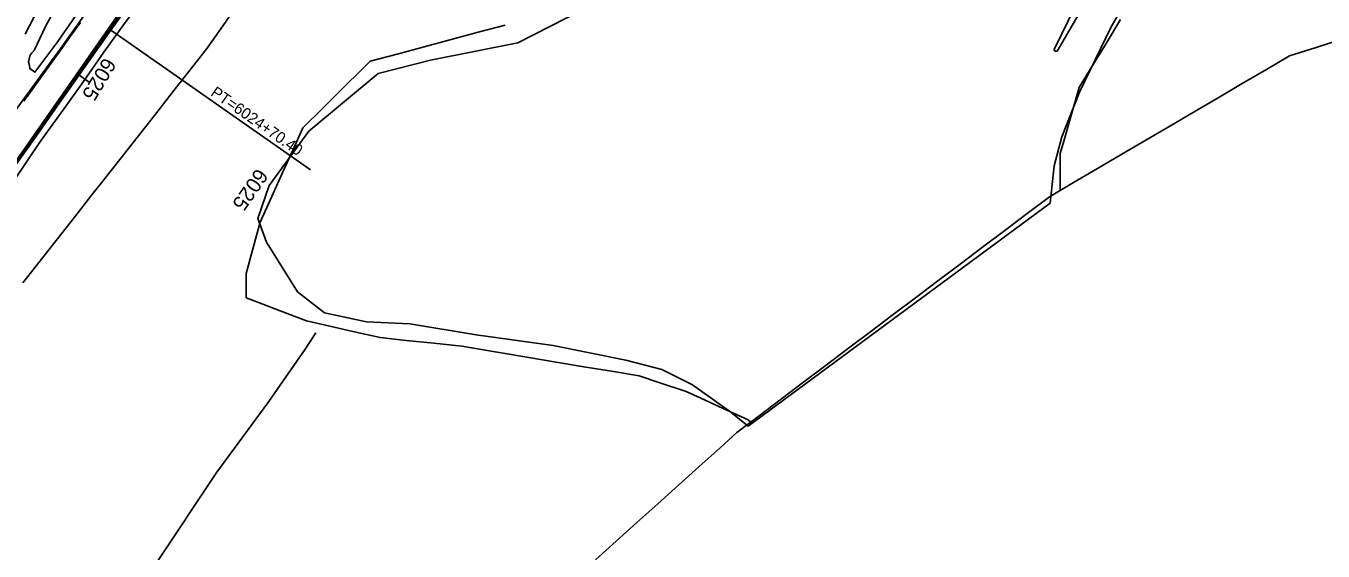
# Model space of a CAD drawing. Extents: x 2132221 to 2141942, y 535736 to 547298.
# Drawn here: x 2137298 to 2137994, y 538942 to 539223 of the extents above; entities that cross this region are included whole.
import ezdxf

# ---------------------------------------------------------------- set-up
doc = ezdxf.new("R2010")
doc.units = 0
for name, color, linetype in [('RD_EX_Conc', 7, 'Continuous'), ('RD_EX_Fence_Other', 7, 'Continuous'), ('RD_EX_H2O', 7, 'Continuous'), ('RD_EX_Misc', 7, 'Continuous'), ('RD_EX_Road', 7, 'Continuous'), ('RD_EX_VEG', 7, 'Continuous'), ('RD_HC_Cl', 7, 'Continuous'), ('RD_HC_Data', 7, 'Continuous'), ('RD_HC_Data_Tic', 7, 'Continuous'), ('RD_HC_TX_Sta50', 7, 'Continuous'), ('TOPO_E_TLIML-Line', 7, 'Continuous')]:
    doc.layers.add(name, color=color, linetype=linetype)

msp = doc.modelspace()

# ---------------------------------------------------------------- linework, layer by layer
at = {"layer": 'RD_EX_Conc'}
for points in [[(2137297.62, 539219.08), (2137309.33, 539241.89), (2137320.01, 539262.99), (2137332.61, 539287.08), (2137349.68, 539315.66)], [(2137386.22, 539279.28), (2137375.65, 539265.67), (2137364.42, 539250.49), (2137352.58, 539233.98), (2137342.73, 539219.91), (2137331.08, 539203.52), (2137316.82, 539183.44), (2137303.12, 539163.77), (2137293.03, 539149.45), (2137281.61, 539133.04), (2137267.61, 539113.07), (2137257.39, 539098.52), (2137236.65, 539069.06), (2137212.4, 539034.24), (2137197.5, 539013.03), (2137179.75, 538987.14)], [(2137362.94, 539275.45), (2137351.65, 539260.12), (2137339.72, 539243.51), (2137329.01, 539228.88), (2137318.09, 539213.54), (2137305.67, 539196.39), (2137289.35, 539173.96)]]:
    msp.add_lwpolyline(points, dxfattribs=at)
at = {"layer": 'RD_EX_Fence_Other'}
msp.add_lwpolyline([(2136945.37, 538272.3), (2136971.41, 538318.47), (2136997.08, 538363.8), (2137022.8, 538408.95), (2137051.26, 538458.29), (2137077.19, 538502.71), (2137097.8, 538537.44), (2137124.86, 538582.37), (2137152.04, 538626.83), (2137178.02, 538666.71), (2137198.91, 538695.64), (2137227.84, 538735.5), (2137257.45, 538774.75), (2137289.09, 538819.98), (2137317.7, 538861.51), (2137345.66, 538902.94), (2137367.4, 538934.33), (2137400.42, 538984.12), (2137428.26, 539021.95), (2137447.73, 539050.02), (2137453.51, 539058.83)], dxfattribs=at)
at = {"layer": 'RD_EX_H2O'}
msp.add_line((2137847.5, 539128.42), (2137685.45, 539008.68), dxfattribs=at)
for points in [[(2137886.46, 539286.47), (2137849.68, 539210.84), (2137849.93, 539210.04)], [(2137895.59, 539249.76), (2137880.13, 539223.04), (2137863.18, 539187.95), (2137853.74, 539164.07), (2137849.61, 539148.37), (2137847.5, 539128.42)], [(2137849.93, 539210.04), (2137851.22, 539210.04), (2137872.96, 539247.48)], [(2137685.45, 539008.68), (2137676.1, 539016.18), (2137655.58, 539030.97), (2137639.12, 539039.08), (2137619.9, 539044.12), (2137580.84, 539052.04), (2137539.51, 539057.84), (2137503.99, 539063.61), (2137480.64, 539064.8), (2137458.25, 539069.56), (2137443.74, 539080.87), (2137427.12, 539107.48), (2137422.46, 539120.23), (2137428.56, 539137.96), (2137449.83, 539167.12), (2137486.95, 539198.05), (2137515.1, 539205.14), (2137561.97, 539214.45), (2137596.87, 539232.3)]]:
    msp.add_lwpolyline(points, dxfattribs=at)
at = {"layer": 'RD_EX_Misc'}
for points in [[(2137351.05, 539232.89), (2137342.37, 539220.66), (2137333.7, 539208.42), (2137325.02, 539196.19), (2137323.9, 539194.61), (2137315.3, 539182.33), (2137306.69, 539170.04), (2137298.09, 539157.76), (2137289.48, 539145.47)], [(2137296.93, 539183.17), (2137302.42, 539190.8), (2137307.91, 539198.44), (2137313.4, 539206.07), (2137316.33, 539210.13), (2137321.82, 539217.77), (2137327.31, 539225.4)]]:
    msp.add_lwpolyline(points, dxfattribs=at)
at = {"layer": 'RD_EX_Road'}
for points in [[(2137371.7, 539292.54), (2137357.19, 539273.64), (2137342.52, 539253.53), (2137326.08, 539230.83), (2137315.06, 539215.22), (2137302.83, 539198.78), (2137300.08, 539200.59), (2137299.94, 539202.26), (2137299.34, 539204.04), (2137300.12, 539207.5), (2137301.1, 539209.13), (2137302.41, 539210.39), (2137308.71, 539223.55), (2137316.49, 539238.12), (2137321.07, 539246.25), (2137329.02, 539260.71), (2137341.13, 539281.49), (2137350.29, 539297.24), (2137356.91, 539308.32)], [(2137390.6, 539276.98), (2137381.06, 539264.66), (2137366.46, 539244.94), (2137351.69, 539226.13), (2137339.88, 539209.47), (2137328.84, 539193.7), (2137317.64, 539177.92), (2137305.73, 539161.76), (2137291.11, 539139.83), (2137277.39, 539118.75), (2137261.14, 539093.92), (2137244.5, 539069.57), (2137229.53, 539048.64), (2137216.9, 539030.62), (2137196.32, 539001.16), (2137178.95, 538975.86), (2137168.15, 538960.62)]]:
    msp.add_lwpolyline(points, dxfattribs=at)
at = {"layer": 'RD_EX_VEG'}
for points in [[(2137411.1, 539234.3), (2137402.48, 539222.02), (2137394.66, 539210.9), (2137385.4, 539199.1), (2137376.15, 539187.29), (2137366.89, 539175.49), (2137357.64, 539163.68), (2137348.38, 539151.88), (2137339.12, 539140.07), (2137333.42, 539132.81), (2137324.17, 539121), (2137314.91, 539109.2), (2137305.66, 539097.39), (2137296.4, 539085.59)], [(2137686.9, 539010.98), (2137685.4, 539012.17), (2137671.77, 539018.43), (2137658.14, 539024.7), (2137652.28, 539027.4), (2137638.02, 539032.05), (2137626.9, 539035.68), (2137612.11, 539038.18), (2137597.32, 539040.67), (2137582.53, 539043.16), (2137567.74, 539045.66), (2137552.95, 539048.15), (2137538.16, 539050.65), (2137531.82, 539051.71), (2137516.9, 539053.26), (2137501.98, 539054.81), (2137488.02, 539056.26), (2137473.4, 539059.62), (2137458.78, 539062.98), (2137448.49, 539065.34), (2137434.47, 539070.68), (2137420.45, 539076.01), (2137416.17, 539077.64), (2137416.17, 539090.73), (2137420.1, 539105.2), (2137423.65, 539118.25), (2137429.86, 539131.91), (2137436.07, 539145.56), (2137442.28, 539159.22), (2137446.62, 539168.76), (2137457.26, 539179.33), (2137467.9, 539189.9), (2137478.55, 539200.47), (2137482.67, 539204.56), (2137497.16, 539208.44), (2137511.65, 539212.32), (2137526.14, 539216.2), (2137540.63, 539220.07), (2137555.13, 539223.95)], [(2137885.29, 539226.92), (2137877.45, 539214.13), (2137869.6, 539201.35), (2137862.96, 539190.52), (2137858.84, 539176.09), (2137854.73, 539161.67), (2137852.82, 539154.97), (2137852.82, 539139.97), (2137852.82, 539135.21)]]:
    msp.add_lwpolyline(points, dxfattribs=at)
at = {"layer": 'RD_HC_Cl'}
msp.add_line((2137342.26, 539222.2), (2136996.48, 538726.24), dxfattribs=at)
msp.add_arc((2138238.15, 538594.85), 1093.7, 40.39109, 144.99812, dxfattribs=at)
at = {"layer": 'RD_HC_Data'}
msp.add_line((2137342.26, 539222.2), (2137450.7, 539146.27), dxfattribs=at)
at = {"layer": 'RD_HC_Data_Tic'}
msp.add_line((2137325.34, 539197.91), (2137331.9, 539193.34), dxfattribs=at)
at = {"layer": 'TOPO_E_TLIML-Line'}
msp.add_lwpolyline([(2137603.47, 538937.01), (2137614.63, 538947.04), (2137625.78, 538957.07), (2137636.93, 538967.11), (2137648.08, 538977.14), (2137659.23, 538987.17), (2137670.38, 538997.2), (2137679.44, 539005.36), (2137691.42, 539014.39), (2137703.39, 539023.43), (2137715.36, 539032.46), (2137727.34, 539041.49), (2137739.31, 539050.53), (2137751.29, 539059.56), (2137763.26, 539068.6), (2137775.23, 539077.63), (2137787.21, 539086.67), (2137799.18, 539095.7), (2137811.16, 539104.74), (2137823.13, 539113.77), (2137835.1, 539122.81), (2137847.07, 539131.83), (2137860, 539139.42), (2137872.94, 539147.01), (2137885.88, 539154.61), (2137898.81, 539162.2), (2137911.75, 539169.79), (2137924.69, 539177.38), (2137937.62, 539184.97), (2137950.56, 539192.57), (2137963.5, 539200.16), (2137975.83, 539207.39), (2137990.11, 539211.97), (2138004.39, 539216.55)], dxfattribs=at)

# ---------------------------------------------------------------- texts
at = {"layer": 'RD_HC_Data'}
msp.add_text('PT=6024+70.40', height=6, rotation=324.99812, dxfattribs=at).set_placement((2137396.66, 539186.55))
at = {"layer": 'RD_HC_TX_Sta50'}
for rotation, p in [(239.11572, (2137340, 539207.07)), (235.11572, (2137421.93, 539147.62))]:
    msp.add_text('6025', height=8, rotation=rotation, dxfattribs=at).set_placement(p)

doc.saveas('drawing.dxf')
